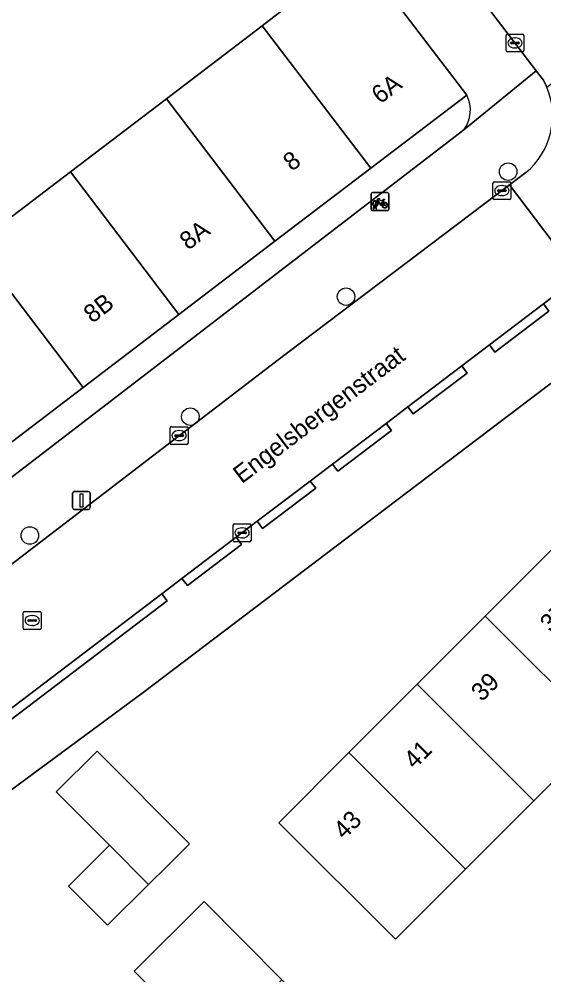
# Model space of a CAD drawing. Extents: x 159960 to 160866, y 382700 to 383354.
# Drawn here: x 160062.8 to 160092.2, y 383157.2 to 383210.7 of the extents above; entities that cross this region are included whole.
import ezdxf

# ---------------------------------------------------------------- set-up
doc = ezdxf.new("R2010")
doc.units = 0
for name, color, linetype in [('IMGEO_Boom', 7, 'Continuous'), ('IMGEO_Erf', 7, 'Continuous'), ('IMGEO_Fietsenrek', 7, 'Continuous'), ('IMGEO_Kolk', 7, 'Continuous'), ('IMGEO_Lichtmast', 7, 'Continuous'), ('IMGEO_Openbare_ruimte_label', 7, 'Continuous'), ('IMGEO_Pand', 7, 'Continuous'), ('IMGEO_Pand_nummerreeks', 7, 'Continuous'), ('IMGEO_Rijbaan_lokaal_open', 7, 'Continuous'), ('IMGEO_Rioolput', 7, 'Continuous'), ('IMGEO_Voetpad_open', 7, 'Continuous')]:
    doc.layers.add(name, color=color, linetype=linetype)

msp = doc.modelspace()

# ---------------------------------------------------------------- linework, layer by layer
at = {"layer": 'IMGEO_Boom'}
for centre in [(160090.197, 383202.176), (160081.127, 383195.18), (160072.413, 383188.462), (160063.433, 383181.809)]:
    msp.add_circle(centre, 0.489, dxfattribs=at)
at = {"layer": 'IMGEO_Erf'}
for points in [[(160139.659, 383226.049), (160069.776, 383173.027), (160054.98, 383162.099), (160054.318, 383161.568), (160043.886, 383151.186), (160088.71, 383106.25), (160113.509, 383131.154)], [(160087.886, 383206.456), (160082.517, 383202.366), (160077.148, 383198.275), (160071.778, 383194.184), (160066.41, 383190.094), (160061.04, 383186.003), (160055.844, 383182.044), (160052.814, 383186.022), (160049.765, 383190.023), (160054.962, 383193.982), (160060.331, 383198.073), (160065.7, 383202.163), (160071.07, 383206.254), (160076.439, 383210.345), (160077.814, 383211.392), (160081.83, 383214.404)], [(160029.081, 383163.976), (160030.576, 383162.332), (160031.679, 383161.996), (160032.597, 383162.207), (160045.83, 383172.362), (160054.384, 383178.911), (160087.717, 383204.52)], [(160095.439, 383170.785), (160091.626, 383166.962), (160087.812, 383163.14), (160087.418, 383162.745), (160083.886, 383159.205), (160077.358, 383165.718), (160081.286, 383169.656), (160085.1, 383173.478), (160088.914, 383177.3), (160092.728, 383181.123)]]:
    msp.add_lwpolyline(points, dxfattribs=at)
for points in [[(160067.779, 383159.99), (160065.592, 383162.187), (160067.886, 383164.471), (160064.912, 383167.457), (160067.206, 383169.741), (160072.367, 383164.557), (160071.126, 383163.321), (160070.073, 383162.274)], [(160081.75, 383152.71), (160086.01, 383148.432), (160090.268, 383144.155), (160086.349, 383140.253), (160082.089, 383144.532), (160077.831, 383148.809), (160073.613, 383153.046), (160069.263, 383157.415), (160073.183, 383161.316), (160077.534, 383156.945)]]:
    msp.add_lwpolyline(points, close=True, dxfattribs=at)
msp.add_arc((160086.232, 383205.625), 1.851, 323.3468, 26.6754, dxfattribs=at)
at = {"layer": 'IMGEO_Fietsenrek'}
for p, q in [((160082.523, 383200.074), (160082.523, 383200.915)), ((160082.523, 383200.915), (160082.523, 383200.074)), ((160082.598, 383200.999), (160083.439, 383200.999)), ((160083.439, 383200.999), (160082.598, 383200.999)), ((160083.523, 383200.924), (160083.523, 383200.083)), ((160083.523, 383200.083), (160083.523, 383200.924)), ((160083.21, 383200.548), (160083.246, 383200.453)), ((160083.448, 383199.999), (160082.607, 383199.999)), ((160082.607, 383199.999), (160083.448, 383199.999)), ((160082.65, 383200.083), (160082.689, 383200.243)), ((160082.684, 383200.083), (160082.65, 383200.083)), ((160082.719, 383200.231), (160082.684, 383200.083)), ((160082.761, 383200.255), (160082.76, 383200.259)), ((160082.802, 383200.083), (160082.768, 383200.225)), ((160082.792, 383200.266), (160082.793, 383200.259)), ((160082.8, 383200.229), (160082.835, 383200.083)), ((160082.835, 383200.083), (160082.802, 383200.083))]:
    msp.add_line(p, q, dxfattribs=at)
for points in [[(160082.857, 383200.473), (160082.805, 383200.383), (160082.765, 383200.358), (160082.766, 383200.405), (160082.821, 383200.499)], [(160082.836, 383200.525), (160082.931, 383200.689), (160083.017, 383200.675), (160083.019, 383200.666), (160082.963, 383200.655), (160082.936, 383200.61), (160083.192, 383200.569)], [(160083.132, 383200.281), (160083.082, 383200.281), (160082.891, 383200.532), (160082.872, 383200.5)], [(160083.179, 383200.544), (160082.922, 383200.585), (160082.905, 383200.556), (160083.072, 383200.336), (160083.179, 383200.544)], [(160083.227, 383200.446), (160083.197, 383200.523), (160083.088, 383200.305), (160083.131, 383200.305)], [(160083.161, 383200.305), (160083.281, 383200.304), (160083.237, 383200.418)], [(160083.257, 383200.425), (160083.312, 383200.28), (160083.162, 383200.28)], [(160083.192, 383200.569), (160083.217, 383200.618), (160083.211, 383200.622), (160083.188, 383200.626), (160083.176, 383200.633), (160083.175, 383200.636), (160083.177, 383200.641), (160083.272, 383200.626), (160083.274, 383200.616), (160083.264, 383200.603), (160083.252, 383200.597), (160083.238, 383200.603), (160083.21, 383200.548)]]:
    msp.add_lwpolyline(points, dxfattribs=at)
for centre, radius, start, end in [((160082.601, 383200.921), 0.0779, 92.4484, 184.2845), ((160082.601, 383200.921), 0.0779, 92.4484, 184.2845), ((160083.445, 383200.921), 0.0779, 2.4484, 94.2845), ((160083.445, 383200.921), 0.0779, 2.4484, 94.2845), ((160082.763, 383200.384), 0.159, 62.6766, 242.1369), ((160082.763, 383200.384), 0.129, 63.3192, 238.903), ((160082.763, 383200.384), 0.129, 283.6043, 43.4302), ((160082.763, 383200.384), 0.159, 283.5766, 46.6042), ((160083.29, 383200.3), 0.159, 113.3408, 178.3217), ((160083.29, 383200.3), 0.159, 187.0065, 105.7708), ((160083.29, 383200.3), 0.129, 113.923, 177.9556), ((160083.29, 383200.3), 0.129, 188.6715, 104.5883), ((160082.601, 383200.077), 0.0779, 182.4484, 274.2845), ((160082.601, 383200.077), 0.0779, 182.4484, 274.2845), ((160082.743, 383200.255), 0.0499, 12.8025, 158.6934), ((160082.763, 383200.384), 0.159, 253.9967, 271.7867), ((160082.743, 383200.255), 0.0174, 12.8025, 163.4502), ((160082.763, 383200.384), 0.129, 253.415, 269.0204), ((160083.445, 383200.077), 0.0779, 272.4484, 4.2845), ((160083.445, 383200.077), 0.0779, 272.4484, 4.2845)]:
    msp.add_arc(centre, radius, start, end, dxfattribs=at)
at = {"layer": 'IMGEO_Kolk'}
for p, q in [((160090.077, 383208.951), (160090.077, 383209.803)), ((160090.152, 383209.877), (160091.004, 383209.877)), ((160090.565, 383209.657), (160090.59, 383209.657)), ((160091.078, 383209.803), (160091.078, 383208.951)), ((160090.336, 383209.371), (160090.336, 383209.383)), ((160090.774, 383209.334), (160090.376, 383209.334)), ((160090.379, 383209.42), (160090.777, 383209.42)), ((160090.588, 383209.097), (160090.563, 383209.097)), ((160090.82, 383209.383), (160090.82, 383209.371)), ((160091.004, 383208.877), (160090.152, 383208.877)), ((160089.346, 383200.687), (160089.346, 383201.539)), ((160089.421, 383201.613), (160090.273, 383201.613)), ((160090.347, 383201.539), (160090.347, 383200.687)), ((160089.605, 383201.107), (160089.605, 383201.119)), ((160090.043, 383201.07), (160089.645, 383201.07)), ((160089.648, 383201.156), (160090.046, 383201.156)), ((160089.834, 383201.393), (160089.859, 383201.393)), ((160090.089, 383201.119), (160090.089, 383201.107)), ((160090.273, 383200.613), (160089.421, 383200.613)), ((160089.857, 383200.833), (160089.832, 383200.833)), ((160071.283, 383186.974), (160071.283, 383187.826)), ((160071.358, 383187.9), (160072.21, 383187.9)), ((160071.771, 383187.68), (160071.796, 383187.68)), ((160072.284, 383187.826), (160072.284, 383186.974)), ((160071.542, 383187.394), (160071.542, 383187.406)), ((160071.98, 383187.357), (160071.582, 383187.357)), ((160071.585, 383187.443), (160071.983, 383187.443)), ((160071.794, 383187.12), (160071.769, 383187.12)), ((160072.026, 383187.406), (160072.026, 383187.394)), ((160072.21, 383186.9), (160071.358, 383186.9)), ((160074.808, 383181.531), (160074.808, 383182.383)), ((160074.883, 383182.457), (160075.735, 383182.457)), ((160075.296, 383182.237), (160075.321, 383182.237)), ((160075.809, 383182.383), (160075.809, 383181.531)), ((160075.067, 383181.951), (160075.067, 383181.963)), ((160075.505, 383181.914), (160075.107, 383181.914)), ((160075.11, 383182), (160075.508, 383182)), ((160075.319, 383181.677), (160075.294, 383181.677)), ((160075.551, 383181.963), (160075.551, 383181.951)), ((160075.735, 383181.457), (160074.883, 383181.457))]:
    msp.add_line(p, q, dxfattribs=at)
for points in [[(160090.077, 383208.951), (160090.077, 383209.803)], [(160090.152, 383209.877), (160091.004, 383209.877)], [(160091.078, 383209.803), (160091.078, 383208.951)], [(160091.004, 383208.877), (160090.152, 383208.877)], [(160089.346, 383200.687), (160089.346, 383201.539)], [(160089.421, 383201.613), (160090.273, 383201.613)], [(160090.347, 383201.539), (160090.347, 383200.687)], [(160090.273, 383200.613), (160089.421, 383200.613)], [(160071.283, 383186.974), (160071.283, 383187.826)], [(160071.358, 383187.9), (160072.21, 383187.9)], [(160072.284, 383187.826), (160072.284, 383186.974)], [(160072.21, 383186.9), (160071.358, 383186.9)], [(160074.808, 383181.531), (160074.808, 383182.383)], [(160074.883, 383182.457), (160075.735, 383182.457)], [(160075.809, 383182.383), (160075.809, 383181.531)], [(160075.735, 383181.457), (160074.883, 383181.457)]]:
    msp.add_lwpolyline(points, dxfattribs=at)
for centre, radius, start, end in [((160090.154, 383209.801), 0.0765, 91.552, 178.448), ((160090.154, 383209.801), 0.0765, 91.552, 178.448), ((160091.002, 383209.801), 0.0765, 1.552, 88.448), ((160091.002, 383209.801), 0.0765, 1.552, 88.448), ((160090.154, 383208.953), 0.0765, 181.552, 268.448), ((160090.154, 383208.953), 0.0765, 181.552, 268.448), ((160090.376, 383209.38), 0.0403, 85.8775, 175.7526), ((160090.373, 383209.37), 0.0366, 178.938, 274.7102), ((160090.777, 383209.377), 0.043, 264.8664, 352.4533), ((160090.781, 383209.382), 0.0386, 1.7309, 96.639), ((160091.002, 383208.953), 0.0765, 271.552, 358.448), ((160091.002, 383208.953), 0.0765, 271.552, 358.448), ((160089.423, 383201.537), 0.0765, 91.552, 178.448), ((160089.423, 383201.537), 0.0765, 91.552, 178.448), ((160090.271, 383201.537), 0.0765, 1.552, 88.448), ((160090.271, 383201.537), 0.0765, 1.552, 88.448), ((160089.645, 383201.116), 0.0403, 85.8775, 175.7526), ((160089.642, 383201.106), 0.0366, 178.938, 274.7102), ((160090.046, 383201.113), 0.043, 264.8664, 352.4533), ((160090.05, 383201.118), 0.0386, 1.7309, 96.639), ((160089.423, 383200.689), 0.0765, 181.552, 268.448), ((160089.423, 383200.689), 0.0765, 181.552, 268.448), ((160090.271, 383200.689), 0.0765, 271.552, 358.448), ((160090.271, 383200.689), 0.0765, 271.552, 358.448), ((160071.36, 383187.824), 0.0765, 91.552, 178.448), ((160071.36, 383187.824), 0.0765, 91.552, 178.448), ((160072.208, 383187.824), 0.0765, 1.552, 88.448), ((160072.208, 383187.824), 0.0765, 1.552, 88.448), ((160071.582, 383187.403), 0.0403, 85.8775, 175.7526), ((160071.579, 383187.393), 0.0366, 178.938, 274.7102), ((160071.983, 383187.4), 0.043, 264.8664, 352.4533), ((160071.987, 383187.405), 0.0386, 1.7309, 96.639), ((160071.36, 383186.976), 0.0765, 181.552, 268.448), ((160071.36, 383186.976), 0.0765, 181.552, 268.448), ((160072.208, 383186.976), 0.0765, 271.552, 358.448), ((160072.208, 383186.976), 0.0765, 271.552, 358.448), ((160074.885, 383182.381), 0.0765, 91.552, 178.448), ((160074.885, 383182.381), 0.0765, 91.552, 178.448), ((160075.733, 383182.381), 0.0765, 1.552, 88.448), ((160075.733, 383182.381), 0.0765, 1.552, 88.448), ((160075.107, 383181.96), 0.0403, 85.8775, 175.7526), ((160075.104, 383181.95), 0.0366, 178.938, 274.7102), ((160075.508, 383181.957), 0.043, 264.8664, 352.4533), ((160075.512, 383181.962), 0.0386, 1.7309, 96.639), ((160074.885, 383181.533), 0.0765, 181.552, 268.448), ((160074.885, 383181.533), 0.0765, 181.552, 268.448), ((160075.733, 383181.533), 0.0765, 271.552, 358.448), ((160075.733, 383181.533), 0.0765, 271.552, 358.448)]:
    msp.add_arc(centre, radius, start, end, dxfattribs=at)
for centre, major_axis, ratio, start_param, end_param in [((160090.564, 383209.377), (-0.387, 0.002), 0.722429, 4.712389, 7.853982), ((160090.589, 383209.377), (-0.39, 0.002), 0.717154, 1.570796, 4.712389), ((160089.833, 383201.113), (-0.387, 0.002), 0.722429, 4.712389, 7.853982), ((160089.858, 383201.113), (-0.39, 0.002), 0.717154, 1.570796, 4.712389), ((160071.77, 383187.4), (-0.387, 0.002), 0.722429, 4.712389, 7.853982), ((160071.795, 383187.4), (-0.39, 0.002), 0.717154, 1.570796, 4.712389), ((160075.295, 383181.957), (-0.387, 0.002), 0.722429, 4.712389, 7.853982), ((160075.32, 383181.957), (-0.39, 0.002), 0.717154, 1.570796, 4.712389)]:
    msp.add_ellipse(centre, major_axis=major_axis, ratio=ratio, start_param=start_param, end_param=end_param, dxfattribs=at)
at = {"layer": 'IMGEO_Lichtmast'}
for p, q in [((160065.819, 383183.37), (160065.819, 383184.17)), ((160065.819, 383184.17), (160065.819, 383183.37)), ((160065.919, 383184.27), (160066.709, 383184.27)), ((160066.709, 383184.27), (160065.919, 383184.27)), ((160066.809, 383184.17), (160066.809, 383183.37)), ((160066.809, 383183.37), (160066.809, 383184.17)), ((160066.709, 383183.27), (160065.919, 383183.27)), ((160065.919, 383183.27), (160066.709, 383183.27))]:
    msp.add_line(p, q, dxfattribs=at)
msp.add_lwpolyline([(160066.239, 383184.145), (160066.389, 383184.145), (160066.389, 383183.395), (160066.239, 383183.395), (160066.239, 383184.145)], dxfattribs=at)
for centre, start, end in [((160065.919, 383184.17), 90, 180), ((160065.919, 383184.17), 90, 180), ((160066.709, 383184.17), 0, 90), ((160066.709, 383184.17), 360, 90), ((160065.919, 383183.37), 180, 270), ((160065.919, 383183.37), 180, 270), ((160066.709, 383183.37), 270, 0), ((160066.709, 383183.37), 270, 0)]:
    msp.add_arc(centre, 0.1, start, end, dxfattribs=at)
at = {"layer": 'IMGEO_Pand'}
for points in [[(160082.517, 383202.366), (160087.886, 383206.456), (160081.83, 383214.404), (160077.814, 383211.392), (160076.439, 383210.345)], [(160071.07, 383206.254), (160077.148, 383198.275), (160082.517, 383202.366), (160076.439, 383210.345)], [(160071.07, 383206.254), (160065.7, 383202.163), (160071.778, 383194.184), (160077.148, 383198.275)], [(160060.331, 383198.073), (160066.41, 383190.094), (160071.778, 383194.184), (160065.7, 383202.163)], [(160060.331, 383198.073), (160054.962, 383193.982), (160061.04, 383186.003), (160066.41, 383190.094)], [(160099.254, 383174.607), (160092.728, 383181.123), (160088.914, 383177.3), (160095.439, 383170.785)], [(160095.439, 383170.785), (160088.914, 383177.3), (160085.1, 383173.478), (160091.626, 383166.962)], [(160081.286, 383169.656), (160087.812, 383163.14), (160091.626, 383166.962), (160085.1, 383173.478)], [(160067.206, 383169.741), (160064.912, 383167.457), (160067.886, 383164.471), (160070.073, 383162.274), (160071.126, 383163.321), (160072.367, 383164.557)], [(160081.286, 383169.656), (160077.358, 383165.718), (160083.886, 383159.205), (160087.418, 383162.745), (160087.812, 383163.14)], [(160067.886, 383164.471), (160065.592, 383162.187), (160067.779, 383159.99), (160070.073, 383162.274)], [(160073.613, 383153.046), (160077.534, 383156.945), (160073.183, 383161.316), (160069.263, 383157.415)]]:
    msp.add_lwpolyline(points, close=True, dxfattribs=at)
at = {"layer": 'IMGEO_Rijbaan_lokaal_open'}
for points in [[(160074.1, 383230.996), (160074.61, 383230.324), (160075.895, 383228.63), (160083.846, 383218.205), (160091.764, 383207.823), (160092.171, 383207.29), (160092.357, 383206.908), (160097.439, 383210.787), (160096.972, 383211.299), (160093.122, 383216.39), (160080.477, 383232.84)], [(160091.192, 383202.128), (160090.278, 383201.437), (160094.167, 383196.29), (160097.576, 383198.881), (160100.603, 383201.181), (160102.165, 383202.369), (160105.164, 383204.648), (160106.341, 383205.542), (160102.49, 383210.638), (160102.245, 383210.451)]]:
    msp.add_lwpolyline(points, dxfattribs=at)
msp.add_lwpolyline([(160074.978, 383181.707), (160076.156, 383182.602), (160079.123, 383184.857), (160080.372, 383185.807), (160083.371, 383188.085), (160084.588, 383189.01), (160087.597, 383191.297), (160089.146, 383192.474), (160092.168, 383194.771), (160094.167, 383196.29), (160090.278, 383201.437), (160077.175, 383191.53), (160056.83, 383175.938), (160055.523, 383174.936), (160053.285, 383173.241), (160045.014, 383166.745), (160042.599, 383164.849), (160046.358, 383159.974), (160048.77, 383161.803), (160058.098, 383168.879), (160070.82, 383178.547), (160071.946, 383179.403)], close=True, dxfattribs=at)
msp.add_arc((160088.571, 383205.299), 4.113, 309.5734, 23.032, dxfattribs=at)
at = {"layer": 'IMGEO_Rioolput'}
for p, q in [((160063.062, 383176.624), (160063.062, 383177.476)), ((160063.137, 383177.55), (160063.989, 383177.55)), ((160064.063, 383177.476), (160064.063, 383176.624)), ((160063.321, 383177.044), (160063.321, 383177.056)), ((160063.759, 383177.007), (160063.361, 383177.007)), ((160063.364, 383177.093), (160063.762, 383177.093)), ((160063.55, 383177.33), (160063.575, 383177.33)), ((160063.805, 383177.056), (160063.805, 383177.044)), ((160063.989, 383176.55), (160063.137, 383176.55)), ((160063.573, 383176.77), (160063.548, 383176.77))]:
    msp.add_line(p, q, dxfattribs=at)
for points in [[(160063.062, 383176.624), (160063.062, 383177.476)], [(160063.137, 383177.55), (160063.989, 383177.55)], [(160064.063, 383177.476), (160064.063, 383176.624)], [(160063.989, 383176.55), (160063.137, 383176.55)]]:
    msp.add_lwpolyline(points, dxfattribs=at)
for centre, radius, start, end in [((160063.139, 383177.474), 0.0765, 91.552, 178.448), ((160063.139, 383177.474), 0.0765, 91.552, 178.448), ((160063.987, 383177.474), 0.0765, 1.552, 88.448), ((160063.987, 383177.474), 0.0765, 1.552, 88.448), ((160063.361, 383177.053), 0.0403, 85.8775, 175.7526), ((160063.358, 383177.043), 0.0366, 178.938, 274.7102), ((160063.762, 383177.05), 0.043, 264.8664, 352.4533), ((160063.766, 383177.055), 0.0386, 1.7309, 96.639), ((160063.139, 383176.626), 0.0765, 181.552, 268.448), ((160063.139, 383176.626), 0.0765, 181.552, 268.448), ((160063.987, 383176.626), 0.0765, 271.552, 358.448), ((160063.987, 383176.626), 0.0765, 271.552, 358.448)]:
    msp.add_arc(centre, radius, start, end, dxfattribs=at)
for centre, major_axis, ratio, start_param, end_param in [((160063.549, 383177.05), (-0.387, 0.002), 0.722429, 4.712389, 7.853982), ((160063.574, 383177.05), (-0.39, 0.002), 0.717154, 1.570796, 4.712389)]:
    msp.add_ellipse(centre, major_axis=major_axis, ratio=ratio, start_param=start_param, end_param=end_param, dxfattribs=at)
at = {"layer": 'IMGEO_Voetpad_open'}
for points in [[(160043.886, 383151.186), (160054.318, 383161.568), (160054.98, 383162.099), (160069.776, 383173.027), (160139.659, 383226.049)], [(160083.846, 383218.205), (160080.723, 383215.828), (160081.83, 383214.404), (160087.886, 383206.456)], [(160087.717, 383204.52), (160091.764, 383207.823), (160083.846, 383218.205)], [(160092.357, 383206.908), (160092.171, 383207.29), (160091.764, 383207.823), (160087.717, 383204.52), (160054.384, 383178.911), (160045.83, 383172.362), (160032.597, 383162.207), (160031.679, 383161.996), (160030.576, 383162.332), (160034.222, 383158.444), (160040.459, 383163.171), (160040.597, 383163.276), (160042.599, 383164.849), (160045.014, 383166.745), (160053.285, 383173.241), (160052.983, 383173.639), (160056.528, 383176.336), (160056.83, 383175.938), (160077.175, 383191.53)], [(160077.175, 383191.53), (160090.278, 383201.437), (160091.192, 383202.128)], [(160094.167, 383196.29), (160092.168, 383194.771), (160092.47, 383194.373), (160089.448, 383192.076), (160089.146, 383192.474), (160087.597, 383191.297), (160087.899, 383190.899), (160084.89, 383188.612), (160084.588, 383189.01), (160083.371, 383188.085), (160083.673, 383187.687), (160080.674, 383185.409), (160080.372, 383185.807), (160079.123, 383184.857), (160079.426, 383184.46), (160076.459, 383182.205), (160076.156, 383182.602), (160074.978, 383181.707), (160075.281, 383181.31), (160072.249, 383179.006), (160071.946, 383179.403), (160070.82, 383178.547), (160071.122, 383178.149), (160058.4, 383168.481)]]:
    msp.add_lwpolyline(points, dxfattribs=at)
for points in [[(160092.168, 383194.771), (160089.146, 383192.474), (160089.448, 383192.076), (160092.47, 383194.373)], [(160087.597, 383191.297), (160084.588, 383189.01), (160084.89, 383188.612), (160087.899, 383190.899)], [(160083.371, 383188.085), (160080.372, 383185.807), (160080.674, 383185.409), (160083.673, 383187.687)], [(160076.156, 383182.602), (160076.459, 383182.205), (160079.426, 383184.46), (160079.123, 383184.857)], [(160074.978, 383181.707), (160071.946, 383179.403), (160072.249, 383179.006), (160075.281, 383181.31)], [(160070.82, 383178.547), (160058.098, 383168.879), (160058.4, 383168.481), (160071.122, 383178.149)]]:
    msp.add_lwpolyline(points, close=True, dxfattribs=at)
for centre, radius, start, end in [((160088.571, 383205.299), 4.113, 309.5734, 23.032), ((160086.232, 383205.625), 1.851, 323.3468, 26.6754)]:
    msp.add_arc(centre, radius, start, end, dxfattribs=at)

# ---------------------------------------------------------------- texts
at = {"layer": 'IMGEO_Openbare_ruimte_label'}
msp.add_text('Engelsbergenstraat', height=1, rotation=37.2823, dxfattribs=at).set_placement((160075.293, 383184.675))
at = {"layer": 'IMGEO_Pand_nummerreeks'}
for s, rotation, p in [('6A', 37.2994, (160083.035, 383205.929)), ('8', 37.3062, (160078.09, 383202.16)), ('8A', 37.3011, (160072.297, 383197.746)), ('8B', 37.3046, (160066.927, 383193.656)), ('37', 45.0656, (160092.582, 383176.332)), ('39', 45.0656, (160088.729, 383172.47)), ('41', 45.0656, (160084.956, 383168.688)), ('43', 45.0656, (160081.023, 383164.747))]:
    msp.add_text(s, height=1, rotation=rotation, dxfattribs=at).set_placement(p)

doc.saveas('drawing.dxf')
